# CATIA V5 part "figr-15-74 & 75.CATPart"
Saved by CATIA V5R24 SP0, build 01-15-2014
Part number: Part1
Bounding box of the stored display mesh (mm): x -68.209 to 30, y -98.209 to 60, z 0 to 98
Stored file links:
  D:\KAVITA\CATIA V5-6R2014 Project_ Kavita\CATIA V5-6R2014_partfiles\Partfiles\c15_catia_v5-6r2014_prt\figr-15-74-75.CATPart
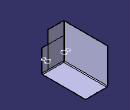
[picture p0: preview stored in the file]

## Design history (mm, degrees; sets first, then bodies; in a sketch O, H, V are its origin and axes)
SheetMetalParameters1: Thickness 1, BendRadius 2, KFactor 0.400515 {= log(min(100,max(20*SheetMetalParameters1.BendRadius,SheetMetalParameters1.Thickness)/SheetMetalParameters1.Thickness))/log(100)/2}, ReliefRadialLength 1, ReliefAxialLength 2, MinimumBendRadius 0
Body1 (main body)
  Sketch1 on xy-plane, origin (0, 0, 0), H (1, 0, 0), V (0, 1, 0)
    line L1 (-30, 60) -> (30, 60)
    line L2 (30, 60) -> (30, -60)
    line L3 (30, -60) -> (-30, -60)
    line L4 (-30, -60) -> (-30, 60)
    length L2 = 120
    length L1 = 60
    distance V L2 = 30
    distance H L1 = 60
    horizontal: L1 H, L3 H
    vertical: L2 V, L4 V
  Wall1: Thickness 1, Profile Sketch1
  d_NewWallOnEdge1: NewWallOnEdge_Edge edge [face of Wall1 | face of Wall1], NewWallOnEdge_Length 98, NewWallOnEdge_HeightLimitOffset 0, NewWallOnEdge_WidthOffset1 0, NewWallOnEdge_WidthOffset2 0, NewWallOnEdge_Angle 90, NewWallOnEdge_BendRadiusValue 2 {= SheetMetalParameters1.BendRadius}, NewWallOnEdge_BendTable SheetMetalParameters1, KFacteur 0.400515 {= log(min(100,max(20*d_NewWallOnEdge1.Radius,SheetMetalParameters1.Thickness)/SheetMetalParameters1.Thickness))/log(100)/2}
  d_NewWallOnEdge2: NewWallOnEdge_Edge edge [face of Wall1 | face of Wall1], NewWallOnEdge_Length 63, NewWallOnEdge_HeightLimitOffset 0, NewWallOnEdge_WidthOffset1 0, NewWallOnEdge_WidthOffset2 0, NewWallOnEdge_Angle 90, NewWallOnEdge_BendRadiusValue 2 {= SheetMetalParameters1.BendRadius}, NewWallOnEdge_BendTable SheetMetalParameters1, KFacteur 0.400515 {= log(min(100,max(20*d_NewWallOnEdge2.Radius,SheetMetalParameters1.Thickness)/SheetMetalParameters1.Thickness))/log(100)/2}
  d_NewWallOnEdge3: NewWallOnEdge_Edge edge [face of d_NewWallOnEdge1 | face of d_NewWallOnEdge1], NewWallOnEdge_Length 44, NewWallOnEdge_HeightLimitOffset 0, NewWallOnEdge_WidthOffset1 0, NewWallOnEdge_WidthOffset2 0, NewWallOnEdge_Angle 90, NewWallOnEdge_BendRadiusValue 2 {= SheetMetalParameters1.BendRadius}, NewWallOnEdge_BendTable SheetMetalParameters1, KFacteur 0.400515 {= log(min(100,max(20*d_NewWallOnEdge3.Radius,SheetMetalParameters1.Thickness)/SheetMetalParameters1.Thickness))/log(100)/2}
  Sketch2 on face of d_NewWallOnEdge3, origin (0, -60, 0), H (-1, 0, 0), V (0, 0, 1)
    circle A1 centre (8.1625, 34.9685) radius 4.4696
    circle A2 centre (8.1625, 23.754) radius 6.7449
    tangency: A2 A1
  SHMMapping1: CATSHMMappingContext d_NewWallOnEdge3, CATSHMMappingObject Sketch2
